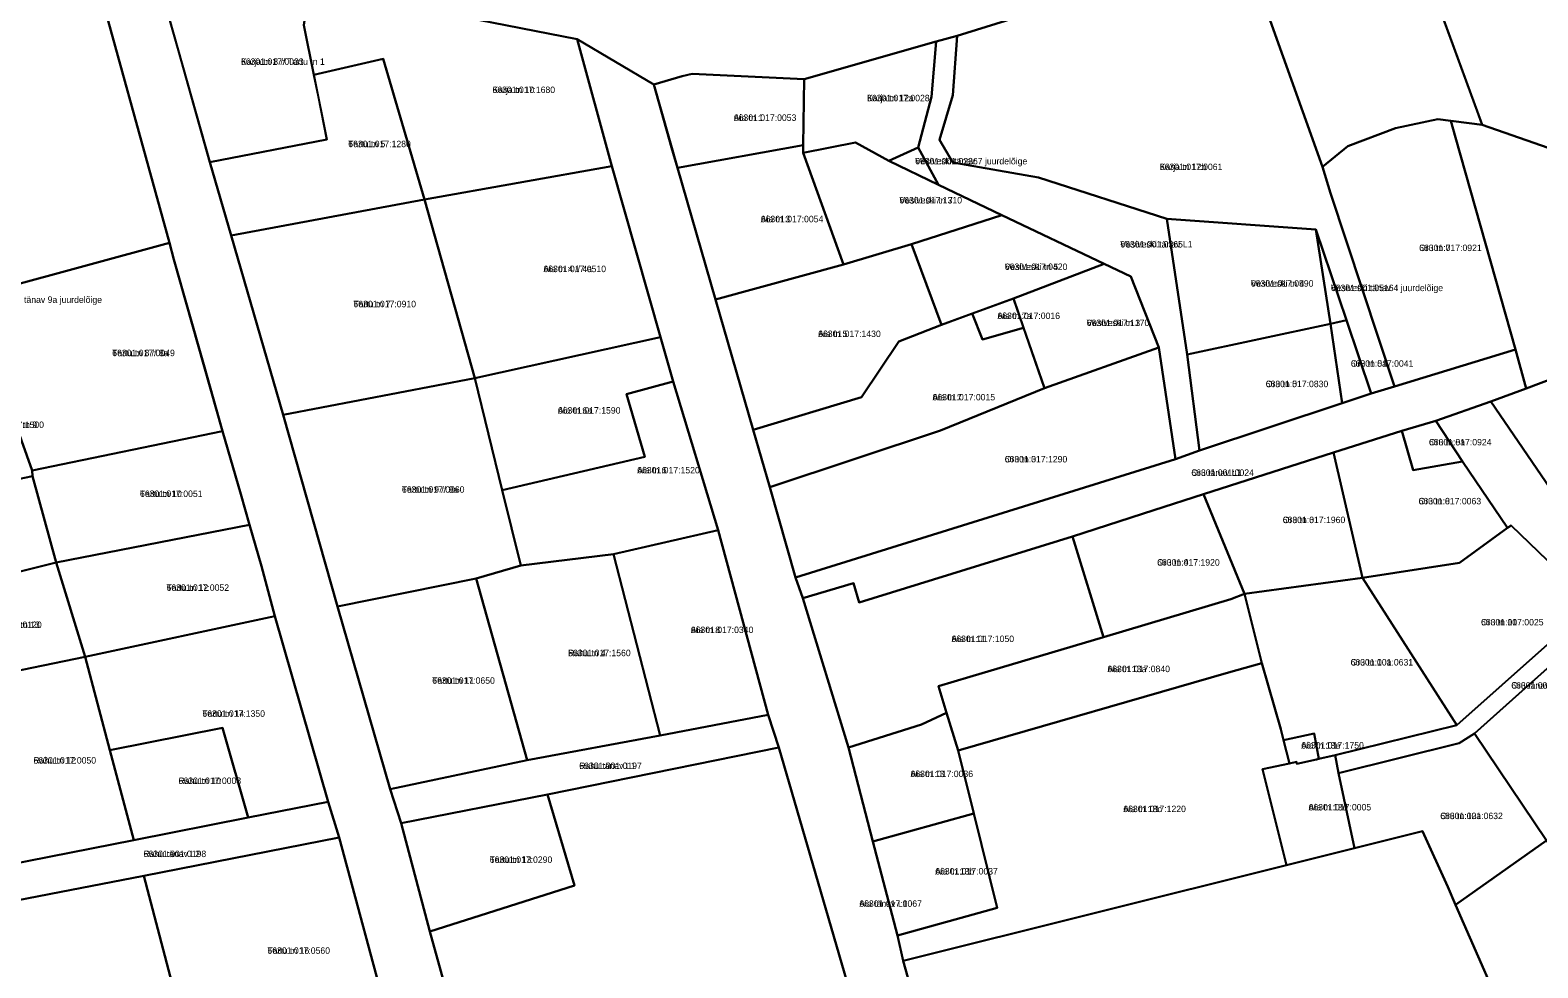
# Model space of a CAD drawing. Extents: x 632278 to 636344, y 6578401 to 6583362.
# Drawn here: x 634226.1 to 634575.5, y 6579911.1 to 6580128.4 of the extents above; entities that cross this region are included whole.
import ezdxf

# ---------------------------------------------------------------- set-up
doc = ezdxf.new("R2010")
doc.units = 0
for name, color, linetype in [('L_AADRESS', 7, 'Continuous'), ('PIIR', 7, 'Continuous'), ('TUNNUS', 7, 'Continuous')]:
    doc.layers.add(name, color=color, linetype=linetype)

msp = doc.modelspace()

# ---------------------------------------------------------------- linework, layer by layer
at = {"layer": 'PIIR'}
for points in [[(634796.84, 6580256.64), (634781.1, 6580253.3), (634732.12, 6580233.33), (634708.48, 6580224.14), (634704.91, 6580222.83), (634676.03, 6580211.71), (634647.97, 6580200.86), (634620.2, 6580190.27), (634596.17, 6580180.31), (634578.31, 6580173.81), (634542.88, 6580160.31), (634507.37, 6580147.83), (634440.93, 6580127.14), (634436.12, 6580125.78), (634405.48, 6580117.09), (634379.51, 6580118.32), (634377.21, 6580117.77), (634370.68, 6580115.86), (634352.92, 6580126.39), (634290.76, 6580138.56), (634257.24, 6580144.92), (634239.36, 6580148.28), (634207.95, 6580154.5)], [(634309.43, 6579898.1), (634297.75, 6579941.29), (634295.22, 6579949.63), (634282.85, 6579992.64), (634279.74, 6580004.23), (634277, 6580013.79), (634274.94, 6580020.93), (634270.74, 6580035.47), (634259.44, 6580075.27), (634258.41, 6580079.17), (634239.36, 6580148.28), (634257.24, 6580144.92), (634255.11, 6580142.72), (634267.8, 6580097.86), (634272.74, 6580080.88), (634284.74, 6580039.26), (634297.36, 6579994.9), (634309.55, 6579952.52), (634312.1, 6579944.67), (634318.74, 6579919.57), (634326.8, 6579890.54)], [(634448.82, 6579793.07), (634399.59, 6579962.17), (634397.15, 6579969.72), (634385.54, 6580012.55), (634375.16, 6580047.04), (634372.2, 6580057.27), (634360.92, 6580096.91), (634352.92, 6580126.39), (634370.68, 6580115.86), (634376.17, 6580096.5), (634384.96, 6580066.02), (634393.65, 6580035.83), (634397.53, 6580022.52), (634403.5, 6580001.6), (634405.22, 6579996.8), (634415.77, 6579962.17), (634421.44, 6579940.42), (634427.1, 6579918.59), (634428.41, 6579912.71), (634454.6, 6579819)], [(634665.82, 6579901.86), (634648.9, 6579922.66), (634629.9, 6579945.27), (634610.54, 6579968.53), (634590.91, 6579992.32), (634588.26, 6579995.4), (634569.33, 6580013.61), (634568.5, 6580013.07), (634558.03, 6580028.45), (634551.85, 6580037.89), (634564.61, 6580042.35), (634593.28, 6580000.44), (634620.65, 6579967.31), (634632.67, 6579952.59), (634655.09, 6579925.92), (634662.07, 6579921.82), (634664.99, 6579919.9), (634684.34, 6579896.64)]]:
    msp.add_lwpolyline(points, dxfattribs=at)
for points in [[(634561.45, 6580109.75), (634542.88, 6580160.31), (634578.31, 6580173.81), (634609.25, 6580093.13), (634611.9, 6580086.21), (634606.27, 6580088.9), (634591.53, 6580095.77), (634581.47, 6580099.94), (634562.64, 6580106.5)], [(634160.64, 6580107.9), (634152.7, 6580136.01), (634150.93, 6580143.48), (634151.81, 6580146.37), (634158.78, 6580160.81), (634160.14, 6580162.23), (634162.35, 6580162.98), (634164.18, 6580163.05), (634181.44, 6580159.69), (634207.95, 6580154.5), (634239.36, 6580148.28), (634258.41, 6580079.17), (634219.59, 6580068.6), (634194.26, 6580061.37), (634174.58, 6580109.77)], [(634525.63, 6580096.76), (634507.37, 6580147.83), (634542.88, 6580160.31), (634562.64, 6580106.5), (634552.34, 6580107.85), (634542.5, 6580105.71), (634531.48, 6580101.52)], [(634440.93, 6580127.14), (634507.37, 6580147.83), (634525.63, 6580096.76), (634527.43, 6580090.65), (634542.3, 6580045.83), (634536.85, 6580044.2), (634531.13, 6580061.26), (634524.07, 6580082.23), (634489.51, 6580084.71), (634459.8, 6580094.28), (634439.94, 6580097.78), (634436.84, 6580102.99), (634439.98, 6580113.4)], [(634257.24, 6580144.92), (634290.76, 6580138.56), (634289.57, 6580129.63), (634291.91, 6580118.12), (634294.9, 6580103.08), (634267.8, 6580097.86), (634260.54, 6580123.73), (634255.11, 6580142.72)], [(634307.91, 6580121.76), (634291.91, 6580118.12), (634289.57, 6580129.63), (634290.76, 6580138.56), (634352.92, 6580126.39), (634360.92, 6580096.91), (634317.52, 6580089.17)], [(634405.48, 6580117.09), (634436.12, 6580125.78), (634435, 6580113), (634431.91, 6580101.21), (634425.12, 6580098.15), (634417.41, 6580102.44), (634405.26, 6580099.98), (634405.28, 6580101.82)], [(634436.12, 6580125.78), (634440.93, 6580127.14), (634439.98, 6580113.4), (634436.84, 6580102.99), (634439.94, 6580097.78), (634459.8, 6580094.28), (634489.51, 6580084.71), (634494.28, 6580053.26), (634497.14, 6580031), (634491.55, 6580029), (634487.68, 6580054.91), (634481.18, 6580071.33), (634475.03, 6580074.25), (634451.3, 6580085.54), (634436.63, 6580092.62), (634431.91, 6580101.21), (634435, 6580113)], [(634267.8, 6580097.86), (634294.9, 6580103.08), (634292.94, 6580113.01), (634291.91, 6580118.12), (634307.91, 6580121.76), (634317.52, 6580089.17), (634272.74, 6580080.88)], [(634370.68, 6580115.86), (634377.21, 6580117.77), (634379.51, 6580118.32), (634405.48, 6580117.09), (634405.28, 6580101.82), (634376.17, 6580096.5), (634374.74, 6580101.28)], [(634527.43, 6580090.65), (634525.63, 6580096.76), (634531.48, 6580101.52), (634542.5, 6580105.71), (634552.34, 6580107.85), (634555.32, 6580107.46), (634556.42, 6580103.56), (634570.36, 6580054.45), (634542.3, 6580045.83)], [(634556.42, 6580103.56), (634555.32, 6580107.46), (634562.64, 6580106.5), (634581.47, 6580099.94), (634591.53, 6580095.77), (634606.27, 6580088.9), (634611.9, 6580086.21), (634615.1, 6580078.5), (634620.47, 6580065.25), (634593.68, 6580053.25), (634572.83, 6580045.36), (634570.36, 6580054.45)], [(634376.17, 6580096.5), (634405.28, 6580101.82), (634405.26, 6580099.98), (634414.61, 6580074.1), (634384.96, 6580066.02)], [(634414.61, 6580074.1), (634405.26, 6580099.98), (634417.41, 6580102.44), (634425.12, 6580098.15), (634436.63, 6580092.62), (634451.3, 6580085.54), (634430.39, 6580078.81)], [(634425.12, 6580098.15), (634431.91, 6580101.21), (634436.63, 6580092.62)], [(634317.52, 6580089.17), (634360.92, 6580096.91), (634372.2, 6580057.27), (634329.19, 6580047.81)], [(634272.74, 6580080.88), (634317.52, 6580089.17), (634329.19, 6580047.81), (634284.74, 6580039.26)], [(634430.39, 6580078.81), (634451.3, 6580085.54), (634475.03, 6580074.25), (634454, 6580066.23), (634437.31, 6580060.17)], [(634524.07, 6580082.23), (634527.47, 6580060.4), (634494.28, 6580053.26), (634489.51, 6580084.71)], [(634531.13, 6580061.26), (634527.47, 6580060.4), (634524.07, 6580082.23)], [(634258.41, 6580079.17), (634259.44, 6580075.27), (634266.35, 6580050.86), (634270.74, 6580035.47), (634226.63, 6580026.37), (634219.57, 6580046.17), (634223.52, 6580047.37), (634220.47, 6580061.26), (634219.85, 6580065.71), (634219.59, 6580068.6)], [(634384.96, 6580066.02), (634414.61, 6580074.1), (634430.39, 6580078.81), (634437.31, 6580060.17), (634427.42, 6580056.31), (634418.81, 6580043.4), (634393.65, 6580035.83)], [(634454, 6580066.23), (634475.03, 6580074.25), (634481.18, 6580071.33), (634487.68, 6580054.91), (634461.2, 6580045.47)], [(634454, 6580066.23), (634456.34, 6580059.46), (634446.8, 6580056.75), (634444.42, 6580062.75)], [(634444.42, 6580062.75), (634446.8, 6580056.75), (634456.34, 6580059.46), (634461.2, 6580045.47), (634437.09, 6580035.68), (634397.53, 6580022.52), (634393.65, 6580035.83), (634418.81, 6580043.4), (634427.42, 6580056.31), (634437.31, 6580060.17)], [(634494.28, 6580053.26), (634527.47, 6580060.4), (634530.18, 6580042.02), (634497.14, 6580031)], [(634531.13, 6580061.26), (634536.85, 6580044.2), (634530.18, 6580042.02), (634527.47, 6580060.4)], [(634174.79, 6580053.65), (634192.39, 6580056.13), (634196.22, 6580055.02), (634199.22, 6580045.33), (634193.01, 6580043.2), (634196.96, 6580028.34), (634203.87, 6580030.12), (634203.62, 6580031.1), (634207.54, 6580032.09), (634206.22, 6580037.77), (634212.13, 6580038.89), (634211.33, 6580043.78), (634219.57, 6580046.17), (634226.63, 6580026.37), (634226.69, 6580025.08), (634185.1, 6580016.35)], [(634329.19, 6580047.81), (634372.2, 6580057.27), (634375.16, 6580047.04), (634364.32, 6580044.1), (634368.58, 6580029.57), (634335.55, 6580021.86)], [(634397.53, 6580022.52), (634437.09, 6580035.68), (634461.2, 6580045.47), (634487.68, 6580054.91), (634491.55, 6580029), (634403.5, 6580001.6)], [(634405.22, 6579996.8), (634403.5, 6580001.6), (634491.55, 6580029), (634497.14, 6580031), (634530.18, 6580042.02), (634536.85, 6580044.2), (634542.3, 6580045.83), (634570.36, 6580054.45), (634572.83, 6580045.36), (634564.61, 6580042.35), (634551.85, 6580037.89), (634543.98, 6580035.59), (634528.14, 6580030.56), (634498.06, 6580020.89), (634486.53, 6580017.2), (634467.66, 6580011.09), (634418.23, 6579995.83), (634416.92, 6580000.25)], [(634564.61, 6580042.35), (634572.83, 6580045.36), (634593.68, 6580053.25), (634598.34, 6580042.43), (634595.56, 6580011.04), (634593.28, 6580000.44)], [(634284.74, 6580039.26), (634329.19, 6580047.81), (634335.55, 6580021.86), (634339.83, 6580004.38), (634329.46, 6580001.34), (634297.36, 6579994.9)], [(634339.83, 6580004.38), (634335.55, 6580021.86), (634368.58, 6580029.57), (634364.32, 6580044.1), (634375.16, 6580047.04), (634385.54, 6580012.55), (634361.29, 6580006.98)], [(634226.63, 6580026.37), (634270.74, 6580035.47), (634274.94, 6580020.93), (634277, 6580013.79), (634232.2, 6580005.03), (634226.69, 6580025.08)], [(634528.14, 6580030.56), (634543.98, 6580035.59), (634546.61, 6580026.5), (634558.03, 6580028.45), (634568.5, 6580013.07), (634557.34, 6580004.98), (634534.91, 6580001.49)], [(634543.98, 6580035.59), (634551.85, 6580037.89), (634558.03, 6580028.45), (634546.61, 6580026.5)], [(634498.06, 6580020.89), (634528.14, 6580030.56), (634534.91, 6580001.49), (634507.5, 6579997.83)], [(634185.1, 6580016.35), (634226.69, 6580025.08), (634232.2, 6580005.03), (634190.56, 6579994.73)], [(634467.66, 6580011.09), (634486.53, 6580017.2), (634498.06, 6580020.89), (634507.5, 6579997.83), (634504.38, 6579996.55), (634474.87, 6579987.79)], [(634232.2, 6580005.03), (634277, 6580013.79), (634279.74, 6580004.23), (634282.85, 6579992.64), (634238.85, 6579983.2)], [(634568.5, 6580013.07), (634569.33, 6580013.61), (634588.26, 6579995.4), (634556.7, 6579967.34), (634534.91, 6580001.49), (634557.34, 6580004.98)], [(634372.11, 6579964.97), (634361.29, 6580006.98), (634385.54, 6580012.55), (634397.15, 6579969.72)], [(634438.47, 6579970.23), (634432.71, 6579967.55), (634415.77, 6579962.17), (634405.22, 6579996.8), (634416.92, 6580000.25), (634418.23, 6579995.83), (634467.66, 6580011.09), (634474.87, 6579987.79), (634443.86, 6579978.58), (634436.66, 6579976.43)], [(634329.46, 6580001.34), (634339.83, 6580004.38), (634361.29, 6580006.98), (634372.11, 6579964.97), (634341.29, 6579959.22)], [(634190.56, 6579994.73), (634232.2, 6580005.03), (634238.85, 6579983.2), (634214.49, 6579978.21), (634195.75, 6579974.73)], [(634341.29, 6579959.22), (634309.55, 6579952.52), (634297.36, 6579994.9), (634329.46, 6580001.34)], [(634511.53, 6579981.71), (634507.5, 6579997.83), (634534.91, 6580001.49), (634556.7, 6579967.34), (634528.51, 6579960.39), (634524.73, 6579959.53), (634523.65, 6579965.43), (634516.6, 6579963.9), (634515.97, 6579966.44)], [(634438.47, 6579970.23), (634436.66, 6579976.43), (634443.86, 6579978.58), (634474.87, 6579987.79), (634504.38, 6579996.55), (634507.5, 6579997.83), (634511.53, 6579981.71), (634503.84, 6579979.59), (634441.19, 6579961.47)], [(634238.85, 6579983.2), (634282.85, 6579992.64), (634295.22, 6579949.63), (634276.63, 6579945.96), (634270.68, 6579966.75), (634244.57, 6579961.58)], [(634529.32, 6579956.26), (634528.51, 6579960.39), (634556.7, 6579967.34), (634588.26, 6579995.4), (634590.91, 6579992.32), (634560.81, 6579965.44), (634557.24, 6579963.18)], [(634577.5, 6579940.63), (634560.81, 6579965.44), (634590.91, 6579992.32), (634610.54, 6579968.53)], [(634244.57, 6579961.58), (634250.13, 6579940.7), (634210.82, 6579933.02), (634205.52, 6579936.36), (634203.71, 6579944.22), (634222.42, 6579947.74), (634214.49, 6579978.21), (634238.85, 6579983.2)], [(634428.41, 6579912.71), (634427.1, 6579918.59), (634450.21, 6579925.06), (634444.79, 6579946.91), (634441.19, 6579961.47), (634503.84, 6579979.59), (634511.53, 6579981.71), (634515.97, 6579966.44), (634516.6, 6579963.9), (634517.93, 6579958.47), (634511.72, 6579957.19), (634517.24, 6579934.89)], [(634309.55, 6579952.52), (634341.29, 6579959.22), (634372.11, 6579964.97), (634397.15, 6579969.72), (634399.59, 6579962.17), (634346.01, 6579951.31), (634312.1, 6579944.67)], [(634415.77, 6579962.17), (634432.71, 6579967.55), (634438.47, 6579970.23), (634441.19, 6579961.47), (634444.79, 6579946.91), (634421.44, 6579940.42)], [(634270.68, 6579966.75), (634276.63, 6579945.96), (634250.13, 6579940.7), (634244.57, 6579961.58)], [(634516.6, 6579963.9), (634523.65, 6579965.43), (634524.73, 6579959.53), (634524.23, 6579959.4), (634519.64, 6579958.44), (634519.56, 6579958.83), (634517.93, 6579958.47)], [(634533.05, 6579938.89), (634529.32, 6579956.26), (634557.24, 6579963.18), (634560.81, 6579965.44), (634577.5, 6579940.63), (634556.45, 6579925.73), (634554.62, 6579929.91), (634548.8, 6579942.83)], [(634382.42, 6579776.42), (634359.7, 6579771.6), (634336.71, 6579856.24), (634359.1, 6579861.95), (634351, 6579896.5), (634326.8, 6579890.54), (634318.74, 6579919.57), (634352.27, 6579930.21), (634346.01, 6579951.31), (634399.59, 6579962.17), (634448.82, 6579793.07), (634407.4, 6579782.73), (634407.97, 6579780.21), (634404.38, 6579779.12), (634397, 6579779.58), (634392.91, 6579778.67)], [(634517.24, 6579934.89), (634511.72, 6579957.19), (634517.93, 6579958.47), (634519.56, 6579958.83), (634519.64, 6579958.44), (634524.23, 6579959.4), (634524.73, 6579959.53), (634528.51, 6579960.39), (634529.32, 6579956.26), (634533.05, 6579938.89)], [(634318.74, 6579919.57), (634312.1, 6579944.67), (634346.01, 6579951.31), (634352.27, 6579930.21)], [(634205.52, 6579936.36), (634210.82, 6579933.02), (634250.13, 6579940.7), (634276.63, 6579945.96), (634295.22, 6579949.63), (634297.75, 6579941.29), (634252.46, 6579932.45), (634208.5, 6579923.96)], [(634421.44, 6579940.42), (634444.79, 6579946.91), (634450.21, 6579925.06), (634427.1, 6579918.59)], [(634252.46, 6579932.45), (634297.75, 6579941.29), (634309.43, 6579898.1), (634264.28, 6579887.44)], [(634557.59, 6579862.31), (634500.94, 6579838.5), (634454.6, 6579819), (634428.41, 6579912.71), (634517.24, 6579934.89), (634533.05, 6579938.89), (634548.8, 6579942.83), (634554.62, 6579929.91), (634556.45, 6579925.73), (634570.22, 6579894.2), (634579.92, 6579871.87)], [(634570.22, 6579894.2), (634556.45, 6579925.73), (634577.5, 6579940.63), (634581.24, 6579935.83), (634596.35, 6579917.35), (634615.16, 6579894.25), (634628.49, 6579878.01), (634623.25, 6579874.72), (634594.58, 6579909.83)], [(634208.5, 6579923.96), (634252.46, 6579932.45), (634264.28, 6579887.44), (634249.32, 6579884.78), (634244.48, 6579904.5), (634214.86, 6579897.24)]]:
    msp.add_lwpolyline(points, close=True, dxfattribs=at)

# ---------------------------------------------------------------- texts
at = {"layer": 'L_AADRESS'}
for s, p in [('Karja tn 8 // Tartu tn 1', (634275, 6580120.4)), ('Karja tn 10', (634333.28, 6580113.87)), ('Karja tn 12a', (634420.07, 6580111.96)), ('Aia tn 1', (634389.19, 6580107.41)), ('Tartu tn 5', (634299.85, 6580101.32)), ('Vesiveski tänav 7 juurdelõige', (634431.22, 6580097.33)), ('Karja tn 12b', (634487.9, 6580096.01)), ('Vesiveski tn 7', (634427.57, 6580088.27)), ('Aia tn 3', (634395.43, 6580083.92)), ('Vesiveski tänav L1', (634478.76, 6580078.07)), ('Oru tn 7', (634548, 6580077.24)), ('Aia tn 4 // 4a', (634345.08, 6580072.36)), ('Vesiveski tn 5', (634451.99, 6580072.86)), ('Vesiveski tn 4', (634509.01, 6580068.99)), ('Vesiveski tänav 4 juurdelõige', (634527.56, 6580067.96)), ('Juhan Kunderi tänav 9a juurdelõige', (634211.23, 6580065.23)), ('Tartu tn 7', (634301.05, 6580064.22)), ('Aia tn 7a', (634450.28, 6580061.49)), ('Vesiveski tn 3', (634470.96, 6580059.86)), ('Aia tn 5', (634408.74, 6580057.32)), ('Tartu tn 8 // 8a', (634245.16, 6580052.88)), ('Oru tn 5a', (634532.16, 6580050.43)), ('Oru tn 5', (634512.44, 6580045.7)), ('Aia tn 7', (634435.24, 6580042.63)), ('Aia tn 6a', (634348.43, 6580039.57)), ('J. Kunderi tn 9', (634214.84, 6580036.24)), ('Oru tn 8a', (634550.27, 6580032.2)), ('Oru tn 3', (634451.96, 6580028.26)), ('Aia tn 6', (634366.81, 6580025.71)), ('Oru tänav L1', (634495.21, 6580025.14)), ('Tartu tn 10', (634251.58, 6580020.25)), ('Tartu tn 9 // 9a', (634312.29, 6580021.23)), ('Oru tn 8', (634547.86, 6580018.54)), ('Oru tn 6', (634516.38, 6580014.19)), ('Oru tn 4', (634487.29, 6580004.34)), ('Tartu tn 12', (634257.73, 6579998.49)), ('J. Kunderi tn 13', (634214.32, 6579989.88)), ('Aia tn 8', (634379.22, 6579988.71)), ('Oru tn 10', (634562.33, 6579990.48)), ('Aia tn 11', (634439.64, 6579986.63)), ('Rahu tn 4', (634350.79, 6579983.35)), ('Oru tn 10a', (634532.1, 6579981.19)), ('Aia tn 13a', (634475.76, 6579979.65)), ('Tartu tn 11', (634319.32, 6579976.95)), ('Oru tänav L3', (634569.35, 6579975.83)), ('Tartu tn 14', (634266.05, 6579969.3)), ('Aia tn 13e', (634520.69, 6579961.94)), ('Rahu tn 12', (634226.92, 6579958.46)), ('Rahu tänav L1', (634353.37, 6579957.2)), ('Rahu tn 10', (634260.53, 6579953.73)), ('Aia tn 13', (634430.13, 6579955.33)), ('Aia tn 13c', (634479.45, 6579947.21)), ('Aia tn 13d', (634522.38, 6579947.6)), ('Oru tn 12a', (634552.89, 6579945.59)), ('Rahu tänav L2', (634252.43, 6579936.79)), ('Tartu tn 13', (634332.63, 6579935.44)), ('Aia tn 13b', (634435.87, 6579932.75)), ('Aia tänav L1', (634418.28, 6579925.26)), ('Tartu tn 16', (634281.12, 6579914.37))]:
    msp.add_text(s, height=1.5, dxfattribs=at).set_placement(p)
at = {"layer": 'TUNNUS'}
for s, p in [('66301:017:0033', (634275, 6580120.4)), ('66301:017:1680', (634333.28, 6580113.87)), ('66301:017:0028', (634420.07, 6580111.96)), ('66301:017:0053', (634389.19, 6580107.41)), ('66301:017:1280', (634299.85, 6580101.32)), ('66301:001:0236', (634431.22, 6580097.33)), ('66301:017:0061', (634487.9, 6580096.01)), ('66301:017:1310', (634427.57, 6580088.27)), ('66301:017:0054', (634395.43, 6580083.92)), ('66301:001:0365', (634478.76, 6580078.07)), ('66301:017:0921', (634548, 6580077.24)), ('66301:017:0510', (634345.08, 6580072.36)), ('66301:017:0420', (634451.99, 6580072.86)), ('66301:017:0590', (634509.01, 6580068.99)), ('66301:001:0516', (634527.56, 6580067.96)), ('66301:017:0910', (634301.05, 6580064.22)), ('66301:017:0016', (634450.28, 6580061.49)), ('66301:017:1170', (634470.96, 6580059.86)), ('66301:017:1430', (634408.74, 6580057.32)), ('66301:017:0049', (634245.16, 6580052.88)), ('66301:017:0041', (634532.16, 6580050.43)), ('66301:017:0830', (634512.44, 6580045.7)), ('66301:017:0015', (634435.24, 6580042.63)), ('66301:017:1590', (634348.43, 6580039.57)), ('66301:017:1500', (634214.84, 6580036.24)), ('66301:017:0924', (634550.27, 6580032.2)), ('66301:017:1290', (634451.96, 6580028.26)), ('66301:017:1520', (634366.81, 6580025.71)), ('66301:001:0024', (634495.21, 6580025.14)), ('66301:017:0051', (634251.58, 6580020.25)), ('66301:017:0060', (634312.29, 6580021.23)), ('66301:017:0063', (634547.86, 6580018.54)), ('66301:017:1960', (634516.38, 6580014.19)), ('66301:017:1920', (634487.29, 6580004.34)), ('66301:017:0052', (634257.73, 6579998.49)), ('66301:017:0120', (634214.32, 6579989.88)), ('66301:017:0340', (634379.22, 6579988.71)), ('66301:017:0025', (634562.33, 6579990.48)), ('66301:017:1050', (634439.64, 6579986.63)), ('66301:017:1560', (634350.79, 6579983.35)), ('66301:001:0631', (634532.1, 6579981.19)), ('66301:017:0840', (634475.76, 6579979.65)), ('66301:017:0650', (634319.32, 6579976.95)), ('66301:001:0636', (634569.35, 6579975.83)), ('66301:017:1350', (634266.05, 6579969.3)), ('66301:017:1750', (634520.69, 6579961.94)), ('66301:017:0050', (634226.92, 6579958.46)), ('66301:001:0197', (634353.37, 6579957.2)), ('66301:017:0008', (634260.53, 6579953.73)), ('66301:017:0036', (634430.13, 6579955.33)), ('66301:017:1220', (634479.45, 6579947.21)), ('66301:017:0005', (634522.38, 6579947.6)), ('66301:001:0632', (634552.89, 6579945.59)), ('66301:001:0198', (634252.43, 6579936.79)), ('66301:017:0290', (634332.63, 6579935.44)), ('66301:017:0037', (634435.87, 6579932.75)), ('66301:017:0067', (634418.28, 6579925.26)), ('66301:017:0560', (634281.12, 6579914.37))]:
    msp.add_text(s, height=1.5, dxfattribs=at).set_placement(p)

doc.saveas('drawing.dxf')
